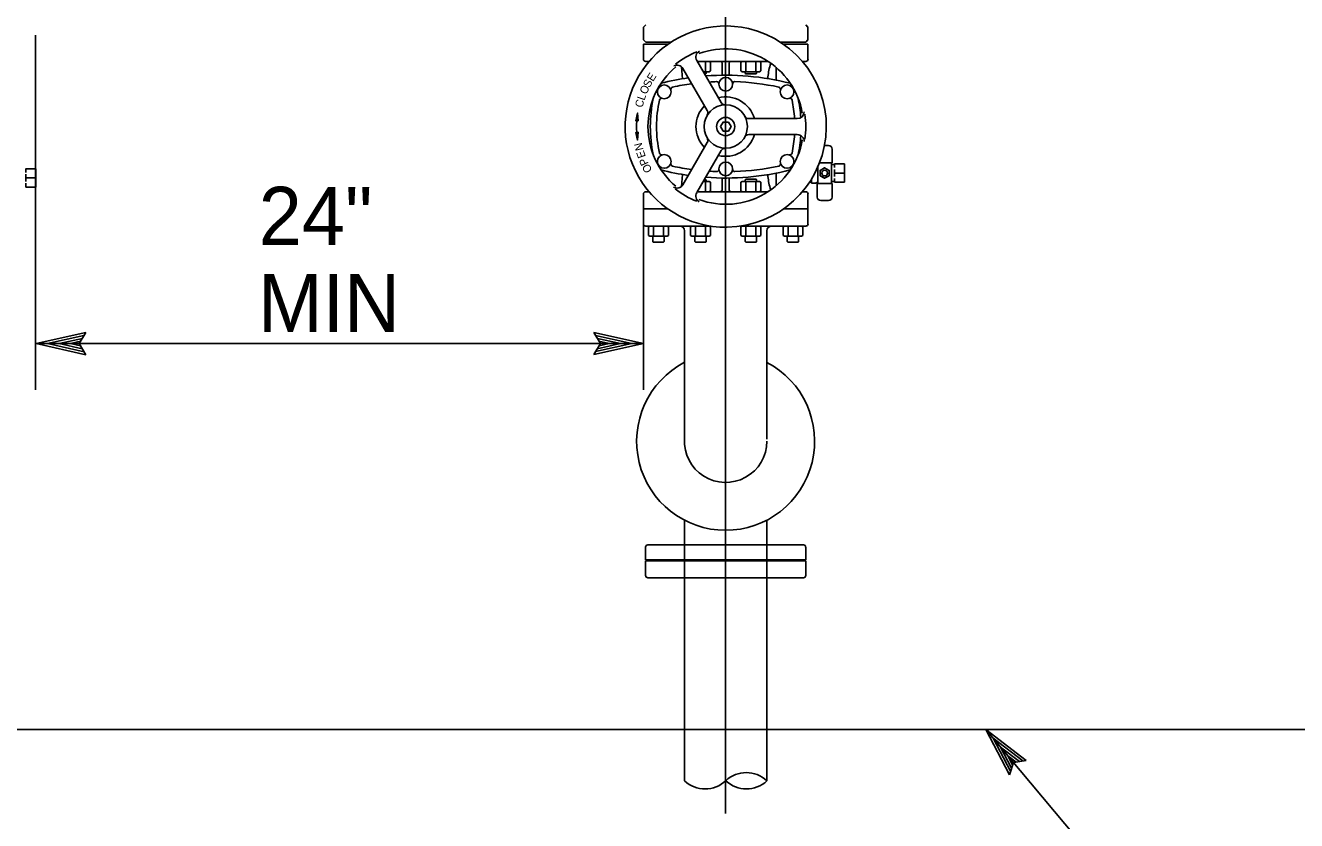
# Model space of a CAD drawing. Extents: x -1680 to 1155, y -802 to 799.
# Drawn here: x 316.4 to 469.8, y -549.1 to -453.1 of the extents above; entities that cross this region are included whole.
import ezdxf

# ---------------------------------------------------------------- set-up
doc = ezdxf.new("R2010")
doc.units = 0
doc.layers.add('Misc CnstDet(22)', color=7, linetype='Continuous')

msp = doc.modelspace()

# ---------------------------------------------------------------- linework, layer by layer
at = {"layer": 'Misc CnstDet(22)'}
for p, q in [((400.86, -548.25), (400.86, -300.3)), ((390.94, -453.35), (391.21, -453.08)), ((390.94, -454.87), (390.94, -453.35)), ((410.8, -453.35), (410.53, -453.08)), ((410.8, -454.87), (410.8, -453.35)), ((317.58, -454.33), (317.58, -497.11)), ((390.94, -454.87), (391.21, -455.15)), ((393.89, -455.42), (390.94, -455.42)), ((390.94, -455.42), (390.94, -457.21)), ((390.94, -455.42), (393.89, -455.42)), ((390.94, -455.42), (393.89, -455.42)), ((394.3, -455.15), (391.21, -455.15)), ((407.44, -455.15), (410.53, -455.15)), ((410.8, -455.42), (407.85, -455.42)), ((407.85, -455.42), (410.8, -455.42)), ((407.85, -455.42), (410.8, -455.42)), ((410.53, -455.15), (410.8, -454.87)), ((410.8, -455.42), (410.8, -457.21)), ((391.62, -457.49), (391.21, -457.49)), ((395.64, -459.58), (395.53, -458.14)), ((398.64, -463.42), (395.71, -458.35)), ((400.31, -462.46), (397.38, -457.38)), ((405.99, -457.49), (397.44, -457.49)), ((398.87, -457.49), (397.44, -457.49)), ((398.43, -458.63), (398.43, -457.59)), ((399.03, -457.58), (398.87, -457.49)), ((399.03, -458.63), (398.87, -458.73)), ((399.03, -458.63), (399.03, -457.58)), ((400.46, -459.15), (400.46, -457.77)), ((401.28, -459.15), (401.28, -457.77)), ((402.71, -457.58), (402.87, -457.49)), ((402.71, -458.63), (402.71, -457.58)), ((402.71, -458.63), (402.87, -458.73)), ((402.87, -457.49), (404.94, -457.49)), ((403.31, -458.63), (403.31, -457.59)), ((404.51, -458.63), (404.51, -457.59)), ((405.1, -457.58), (404.94, -457.49)), ((405.1, -458.63), (404.94, -458.73)), ((405.1, -458.63), (405.1, -457.58)), ((406.94, -459.73), (406.94, -458.2)), ((410.53, -457.49), (410.12, -457.49)), ((398.87, -458.73), (398.16, -458.73)), ((398.52, -458.94), (398.28, -458.94)), ((398.46, -459), (398.52, -458.94)), ((398.52, -458.94), (398.52, -458.73)), ((402.87, -458.73), (404.94, -458.73)), ((403.22, -458.94), (403.22, -458.73)), ((403.28, -459), (403.22, -458.94)), ((403.28, -459), (404.53, -459)), ((404.53, -459), (404.6, -458.94)), ((404.6, -458.94), (404.6, -458.73)), ((403.66, -464.39), (409.51, -464.39)), ((403.66, -466.32), (409.51, -466.32)), ((398.64, -467.28), (395.71, -472.36)), ((412.81, -467.65), (412.79, -467.65)), ((412.81, -467.65), (413.29, -467.65)), ((400.31, -468.25), (397.38, -473.32)), ((413.71, -469.72), (413.71, -468.06)), ((316.39, -470.88), (316.39, -470.43)), ((316.39, -470.43), (317.61, -470.43)), ((317.61, -470.43), (317.61, -471.53)), ((411.98, -470.96), (411.98, -470.24)), ((411.98, -470.96), (411.98, -472.2)), ((412.81, -469.72), (412.2, -469.72)), ((412.81, -469.72), (413.71, -469.72)), ((413.64, -470.96), (413.64, -469.72)), ((413.64, -470.96), (413.64, -472.2)), ((413.65, -469.92), (413.96, -469.92)), ((414, -470.3), (414, -469.85)), ((414, -469.85), (415.22, -469.85)), ((414, -470.96), (414, -470.53)), ((414, -470.96), (414, -471.38)), ((415.09, -470.96), (414.13, -470.96)), ((415.22, -469.85), (415.22, -470.96)), ((415.22, -470.96), (415.22, -472.06)), ((316.39, -471.53), (316.39, -471.11)), ((316.39, -471.53), (316.39, -471.96)), ((316.39, -472.18), (316.39, -472.64)), ((317.48, -471.53), (316.52, -471.53)), ((317.61, -471.53), (317.61, -472.64)), ((395.64, -471.13), (395.53, -472.57)), ((398.87, -471.98), (398.16, -471.98)), ((398.52, -471.77), (398.28, -471.77)), ((398.43, -472.08), (398.43, -473.12)), ((398.52, -471.77), (398.52, -471.98)), ((399.03, -472.07), (398.87, -471.98)), ((399.03, -472.07), (399.03, -473.12)), ((400.46, -471.56), (400.46, -472.94)), ((401.28, -471.56), (401.28, -472.94)), ((402.71, -472.07), (402.87, -471.98)), ((402.71, -472.07), (402.71, -473.12)), ((402.87, -471.98), (404.94, -471.98)), ((403.28, -471.71), (403.22, -471.77)), ((403.22, -471.77), (403.22, -471.98)), ((403.28, -471.71), (404.53, -471.71)), ((403.31, -472.08), (403.31, -473.12)), ((404.51, -472.08), (404.51, -473.12)), ((404.53, -471.71), (404.6, -471.77)), ((404.6, -471.77), (404.6, -471.98)), ((405.1, -472.07), (404.94, -471.98)), ((405.1, -472.07), (405.1, -473.12)), ((406.94, -470.97), (406.94, -472.51)), ((411.21, -472.06), (410.99, -472.06)), ((411.21, -471.72), (411.21, -472.16)), ((411.21, -472.16), (411.76, -472.16)), ((411.81, -472.06), (411.81, -472.13)), ((411.84, -472.11), (411.98, -472.11)), ((411.92, -472.2), (411.92, -473.85)), ((412.81, -472.2), (411.92, -472.2)), ((412.81, -472.2), (413.71, -472.2)), ((413.65, -471.99), (413.96, -471.99)), ((413.71, -472.2), (413.71, -473.85)), ((414, -471.61), (414, -472.06)), ((414, -472.06), (415.22, -472.06)), ((316.39, -472.64), (317.61, -472.64)), ((390.94, -475.29), (390.94, -473.49)), ((390.94, -474.77), (390.94, -473.49)), ((391.21, -473.22), (391.62, -473.22)), ((391.56, -473.22), (391.56, -473.15)), ((405.99, -473.22), (397.44, -473.22)), ((398.87, -473.22), (397.44, -473.22)), ((399.03, -473.12), (398.87, -473.22)), ((402.71, -473.12), (402.87, -473.22)), ((402.87, -473.22), (404.94, -473.22)), ((405.1, -473.12), (404.94, -473.22)), ((410.53, -473.22), (410.12, -473.22)), ((410.18, -473.22), (410.18, -473.15)), ((410.8, -475.29), (410.8, -473.49)), ((393.89, -475.29), (390.94, -475.29)), ((390.94, -475.29), (393.89, -475.29)), ((390.94, -475.29), (390.94, -477.08)), ((407.85, -475.29), (410.8, -475.29)), ((410.8, -475.29), (407.85, -475.29)), ((410.8, -475.29), (410.8, -477.08)), ((412.81, -474.27), (412.33, -474.27)), ((412.81, -474.27), (413.29, -474.27)), ((390.94, -477.08), (390.94, -497.11)), ((391.21, -477.36), (399.04, -477.36)), ((391.56, -477.45), (391.72, -477.36)), ((391.56, -478.5), (391.56, -477.45)), ((391.56, -478.5), (391.72, -478.59)), ((393.79, -477.36), (391.72, -477.36)), ((393.79, -478.59), (391.72, -478.59)), ((392.07, -479.22), (392.07, -478.59)), ((392.16, -478.5), (392.16, -477.45)), ((393.35, -478.5), (393.35, -477.45)), ((393.44, -479.22), (393.44, -478.59)), ((393.95, -477.45), (393.79, -477.36)), ((393.95, -478.5), (393.79, -478.59)), ((393.95, -478.5), (393.95, -477.45)), ((395.9, -477.91), (395.9, -503.05)), ((396.64, -477.45), (396.8, -477.36)), ((396.64, -478.5), (396.64, -477.45)), ((396.64, -478.5), (396.8, -478.59)), ((398.87, -477.36), (396.8, -477.36)), ((398.87, -478.59), (396.8, -478.59)), ((397.14, -479.22), (397.14, -478.59)), ((397.23, -478.5), (397.23, -477.45)), ((398.43, -478.5), (398.43, -477.45)), ((398.52, -479.22), (398.52, -478.59)), ((399.03, -477.45), (398.87, -477.36)), ((399.03, -478.5), (398.87, -478.59)), ((399.03, -478.5), (399.03, -477.45)), ((402.69, -477.36), (410.53, -477.36)), ((402.71, -477.45), (402.87, -477.36)), ((402.71, -478.5), (402.71, -477.45)), ((402.71, -478.5), (402.87, -478.59)), ((404.94, -477.36), (402.87, -477.36)), ((404.94, -478.59), (402.87, -478.59)), ((403.22, -479.22), (403.22, -478.59)), ((403.31, -478.5), (403.31, -477.45)), ((404.51, -478.5), (404.51, -477.45)), ((404.6, -479.22), (404.6, -478.59)), ((405.1, -477.45), (404.94, -477.36)), ((405.1, -478.5), (404.94, -478.59)), ((405.1, -478.5), (405.1, -477.45)), ((405.84, -477.91), (405.84, -503.05)), ((407.79, -477.45), (407.95, -477.36)), ((407.79, -478.5), (407.79, -477.45)), ((407.79, -478.5), (407.95, -478.59)), ((410.02, -477.36), (407.95, -477.36)), ((410.02, -478.59), (407.95, -478.59)), ((408.29, -479.22), (408.29, -478.59)), ((408.39, -478.5), (408.39, -477.45)), ((409.58, -478.5), (409.58, -477.45)), ((409.67, -479.22), (409.67, -478.59)), ((410.18, -477.45), (410.02, -477.36)), ((410.18, -478.5), (410.02, -478.59)), ((410.18, -478.5), (410.18, -477.45)), ((392.13, -479.29), (392.07, -479.22)), ((393.38, -479.29), (392.13, -479.29)), ((393.38, -479.29), (393.44, -479.22)), ((397.21, -479.29), (397.14, -479.22)), ((398.46, -479.29), (397.21, -479.29)), ((398.46, -479.29), (398.52, -479.22)), ((403.28, -479.29), (403.22, -479.22)), ((404.53, -479.29), (403.28, -479.29)), ((404.53, -479.29), (404.6, -479.22)), ((408.36, -479.29), (408.29, -479.22)), ((409.61, -479.29), (408.36, -479.29)), ((409.61, -479.29), (409.67, -479.22)), ((317.65, -491.53), (323.65, -490.2)), ((319.04, -491.52), (323.41, -490.56)), ((320.41, -491.53), (323.23, -490.9)), ((323.65, -490.2), (322.85, -491.53)), ((323.65, -490.2), (323.65, -490.2)), ((385.74, -491.53), (384.94, -490.19)), ((384.94, -490.19), (384.94, -490.19)), ((384.94, -490.19), (390.94, -491.53)), ((385.15, -490.54), (389.56, -491.53)), ((385.39, -490.9), (388.17, -491.52)), ((317.58, -491.53), (390.94, -491.53)), ((323.65, -492.87), (317.65, -491.53)), ((317.65, -491.53), (317.65, -491.53)), ((323.43, -492.51), (319.03, -491.53)), ((323.2, -492.15), (320.41, -491.53)), ((321.79, -491.53), (323, -491.26)), ((323.02, -491.8), (321.79, -491.53)), ((322.85, -491.53), (323.65, -492.87)), ((390.94, -491.53), (384.94, -492.86)), ((384.94, -492.86), (385.74, -491.53)), ((389.55, -491.53), (385.17, -492.5)), ((388.17, -491.52), (385.35, -492.15)), ((385.56, -491.25), (386.79, -491.52)), ((386.79, -491.52), (385.58, -491.79)), ((390.94, -491.53), (390.94, -491.53)), ((323.65, -492.87), (323.65, -492.87)), ((384.94, -492.86), (384.94, -492.86)), ((395.9, -530.77), (395.9, -512.84)), ((405.84, -530.77), (405.84, -512.84)), ((391.2, -517.62), (391.2, -516.08)), ((391.46, -515.82), (395.37, -515.82)), ((406.37, -515.82), (395.37, -515.82)), ((410.26, -515.82), (406.36, -515.82)), ((410.52, -517.62), (410.52, -516.08)), ((391.2, -517.62), (405.25, -517.62)), ((391.2, -519.5), (391.2, -517.76)), ((391.2, -517.76), (405.54, -517.76)), ((405.25, -517.62), (410.52, -517.62)), ((405.54, -517.76), (410.53, -517.76)), ((410.53, -519.5), (410.53, -517.76)), ((391.48, -519.78), (395.88, -519.78)), ((408.4, -519.78), (395.88, -519.78)), ((408.4, -519.78), (410.25, -519.78)), ((395.9, -530.77), (395.9, -544.28)), ((405.84, -530.77), (405.84, -544.28)), ((212.09, -538.09), (565.93, -538.09)), ((437.14, -541.83), (432.27, -538.09)), ((432.27, -538.09), (432.27, -538.09)), ((432.27, -538.09), (435.1, -543.55)), ((436.73, -541.89), (433.15, -539.15)), ((433.16, -539.16), (435.22, -543.13)), ((436.31, -541.95), (434.04, -540.21)), ((434.04, -540.21), (435.37, -542.78)), ((435.93, -542.03), (434.93, -541.27)), ((434.93, -541.27), (435.5, -542.37)), ((435.1, -543.55), (435.6, -542.08)), ((435.6, -542.08), (437.14, -541.83)), ((437.14, -541.83), (437.14, -541.83)), ((435.1, -543.55), (435.1, -543.55))]:
    msp.add_line(p, q, dxfattribs=at)
for points in [[(390.32, -464.66), (390.01, -464.64), (390.23, -463.72)], [(400.55, -465.91), (400.23, -465.35), (400.55, -464.8), (401.19, -464.8), (401.51, -465.35), (401.19, -465.91)], [(390.32, -466.04), (390.01, -466.07), (390.23, -466.98)], [(412.26, -471.28), (412.81, -471.59), (413.36, -471.28), (413.36, -470.64), (412.81, -470.32), (412.26, -470.64)]]:
    msp.add_lwpolyline(points, close=True, dxfattribs=at)
msp.add_lwpolyline([(432.27, -538.09), (477.44, -592.04), (486.56, -592.04)], dxfattribs=at)
for centre, radius in [((400.87, -460.25), 0.828), ((393.46, -461.16), 0.828), ((408.28, -461.16), 0.828), ((400.87, -465.35), 2.62), ((400.87, -465.35), 1.1), ((393.46, -469.55), 0.828), ((408.28, -469.55), 0.828), ((400.87, -470.46), 0.828), ((412.81, -470.96), 0.345)]:
    msp.add_circle(centre, radius, dxfattribs=at)
for centre, radius, start, end in [((400.87, -465.35), 12.14, 76.8634, 270.7347), ((400.87, -465.35), 12.14, 270.9106, 76.8634), ((400.87, -465.35), 9.66, 110.954, 128.8267), ((398.1, -456.97), 0.828, 118.6865, 210), ((400.87, -465.35), 9.38, 9.8969, 110.1031), ((391.21, -457.21), 0.276, 180, 270), ((400.87, -465.35), 9.38, 129.8969, 230.1031), ((394.99, -458.76), 0.828, 30, 118.2085), ((400.18, -457.77), 0.276, 0, 90), ((401.56, -457.77), 0.276, 90, 180), ((416.65, -460.64), 10.77, 165.4239, 174.2397), ((407.13, -458.21), 0.95, 148.9584, 162.6862), ((410.53, -457.21), 0.276, 270, 0), ((400.87, -490.74), 31.59, 98.2117, 104.2666), ((400.87, -490.74), 30.83, 97.6469, 101.9908), ((400.87, -490.74), 31.59, 75.7334, 94.3855), ((400.87, -490.74), 30.83, 92.0678, 93.7076), ((399.77, -460.2), 0.276, 357.4512, 92.0678), ((401.97, -460.2), 0.276, 87.9322, 182.5489), ((400.87, -490.74), 30.83, 78.0092, 87.9322), ((394.52, -460.85), 0.276, 101.9908, 196.6074), ((407.22, -460.85), 0.276, 343.3926, 78.0092), ((407.92, -465.35), 16.15, 167.8489, 192.1511), ((407.92, -465.35), 15.39, 168.0139, 180), ((393.13, -462.21), 0.276, 72.3405, 168.0139), ((400.87, -465.35), 3.59, 135.6185, 224.3815), ((400.87, -465.35), 3.59, 15.6185, 104.3815), ((400.79, -462.18), 0.552, 210, 271.4281), ((408.61, -462.21), 0.276, 11.9861, 107.6595), ((393.82, -465.35), 15.39, 3.5967, 11.9861), ((393.82, -465.35), 16.15, 3.9315, 12.1511), ((400.87, -465.35), 10.76, 173.2861, 186.7139), ((398.16, -463.7), 0.552, 328.5719, 30), ((403.66, -463.84), 0.552, 208.5719, 270), ((409.51, -463.56), 0.828, 270, 358.2085), ((400.87, -465.35), 9.66, 350.954, 8.8267), ((407.92, -465.35), 15.39, 180, 191.9861), ((400.87, -465.35), 3.59, 255.6185, 344.3815), ((403.66, -466.87), 0.552, 90, 151.4281), ((393.82, -465.35), 15.39, 348.0139, 356.4033), ((409.51, -467.15), 0.828, 358.6865, 90), ((400.87, -465.35), 9.38, 249.8969, 350.1031), ((398.16, -467.01), 0.552, 330, 31.4281), ((393.82, -465.35), 16.15, 347.8489, 356.0685), ((413.29, -468.06), 0.414, 0, 90), ((393.13, -468.49), 0.276, 191.9861, 287.6595), ((400.79, -468.53), 0.552, 88.5719, 150), ((408.61, -468.49), 0.276, 252.3405, 348.0139), ((316.36, -470.46), 0.0345, 270, 0), ((400.87, -439.97), 31.59, 255.7334, 261.7884), ((394.52, -469.86), 0.276, 163.3926, 258.0092), ((400.87, -439.97), 30.83, 258.0092, 262.3531), ((400.87, -439.97), 31.59, 265.6145, 284.2666), ((400.87, -439.97), 30.83, 266.2924, 267.9322), ((399.77, -470.51), 0.276, 267.9322, 2.5489), ((401.97, -470.51), 0.276, 177.4512, 272.0678), ((400.87, -439.97), 30.83, 272.0678, 281.9908), ((407.22, -469.86), 0.276, 281.9908, 16.6074), ((413.65, -469.89), 0.0345, 254.1733, 270), ((413.96, -469.89), 0.0345, 270, 0), ((394.99, -471.94), 0.828, 238.6865, 330), ((416.65, -470.07), 10.77, 185.7603, 194.5761), ((411.76, -472.11), 0.0482, 270, 332.7204), ((411.84, -472.16), 0.0482, 90, 152.7204), ((413.96, -472.03), 0.0345, 0, 90), ((316.36, -472.6), 0.0345, 0, 90), ((391.21, -473.49), 0.276, 90, 180), ((400.87, -465.35), 9.66, 230.954, 248.8267), ((398.1, -473.74), 0.828, 150, 238.2085), ((400.18, -472.94), 0.276, 270, 0), ((401.56, -472.94), 0.276, 180, 270), ((407.13, -472.5), 0.95, 197.3138, 211.0416), ((410.53, -473.49), 0.276, 0, 90), ((412.33, -473.85), 0.414, 180, 270), ((413.29, -473.85), 0.414, 270, 0), ((390.66, -474.77), 0.276, 348.2317, 0), ((391.21, -477.08), 0.276, 180, 270), ((410.53, -477.08), 0.276, 270, 0), ((395.35, -477.91), 0.552, 0, 90), ((406.39, -477.91), 0.552, 90, 180), ((410.53, -477.08), 0.276, 270, 320.9284), ((400.86, -503.32), 10.74, 117.5041, 62.4289), ((400.86, -503.32), 4.97, 176.9128, 359.9994), ((391.46, -516.08), 0.258, 90, 180), ((410.26, -516.08), 0.258, 0, 90), ((391.48, -519.5), 0.279, 180, 270), ((410.25, -519.5), 0.279, 270, 0), ((398.39, -541.66), 3.61, 226.5226, 313.5571), ((403.35, -546.89), 3.6, 46.3237, 133.5967), ((403.36, -541.66), 3.61, 226.461, 313.4594)]:
    msp.add_arc(centre, radius, start, end, dxfattribs=at)

# ---------------------------------------------------------------- texts
for s, height, rotation, p in [('S', 0.966, 62.0107, (391.68, -460.73)), ('E', 0.966, 57.3232, (392.09, -459.98)), ('L', 0.966, 71.3857, (391.06, -462.26)), ('O', 0.966, 66.6982, (391.32, -461.53)), ('C', 0.966, 76.0732, (390.83, -463.12)), ('N', 0.966, 104.3391, (390.96, -468.12)), ('E', 0.966, 109.3391, (391.24, -468.96)), ('P', 0.966, 114.3391, (391.6, -469.8)), ('O', 0.966, 119.3391, (392.04, -470.61)), ('24"', 7, 360, (344.51, -479.62)), ('MIN', 7, 360, (344.42, -490.12))]:
    msp.add_text(s, height=height, rotation=rotation, dxfattribs=at).set_placement(p)

doc.saveas('drawing.dxf')
